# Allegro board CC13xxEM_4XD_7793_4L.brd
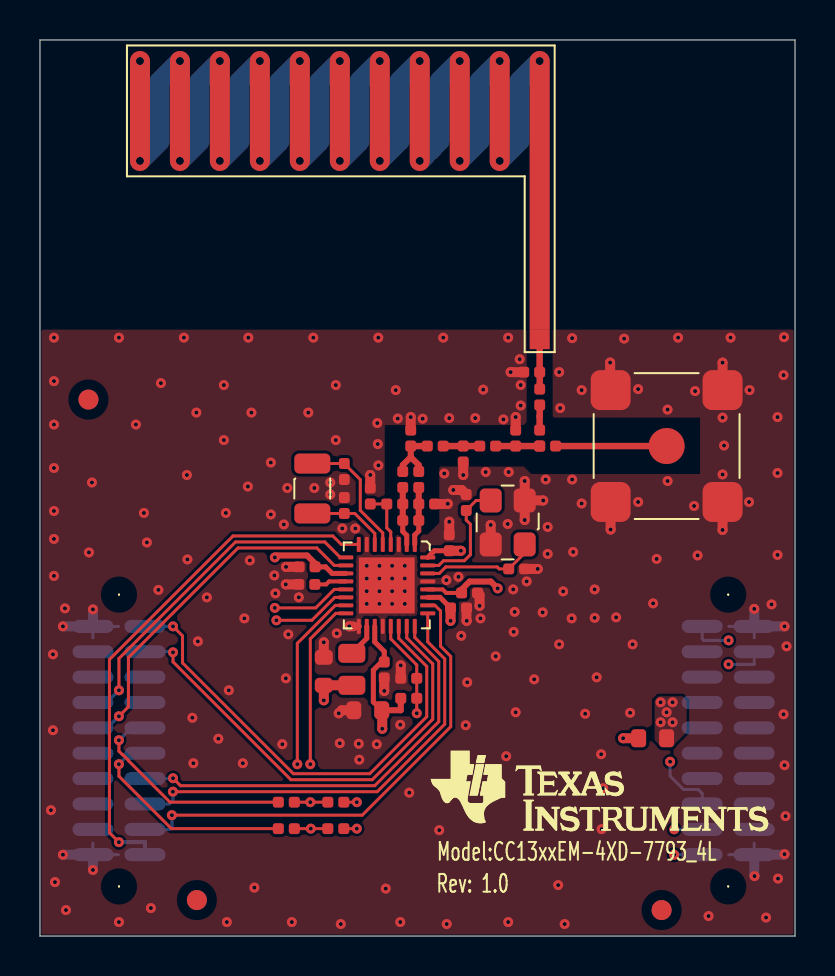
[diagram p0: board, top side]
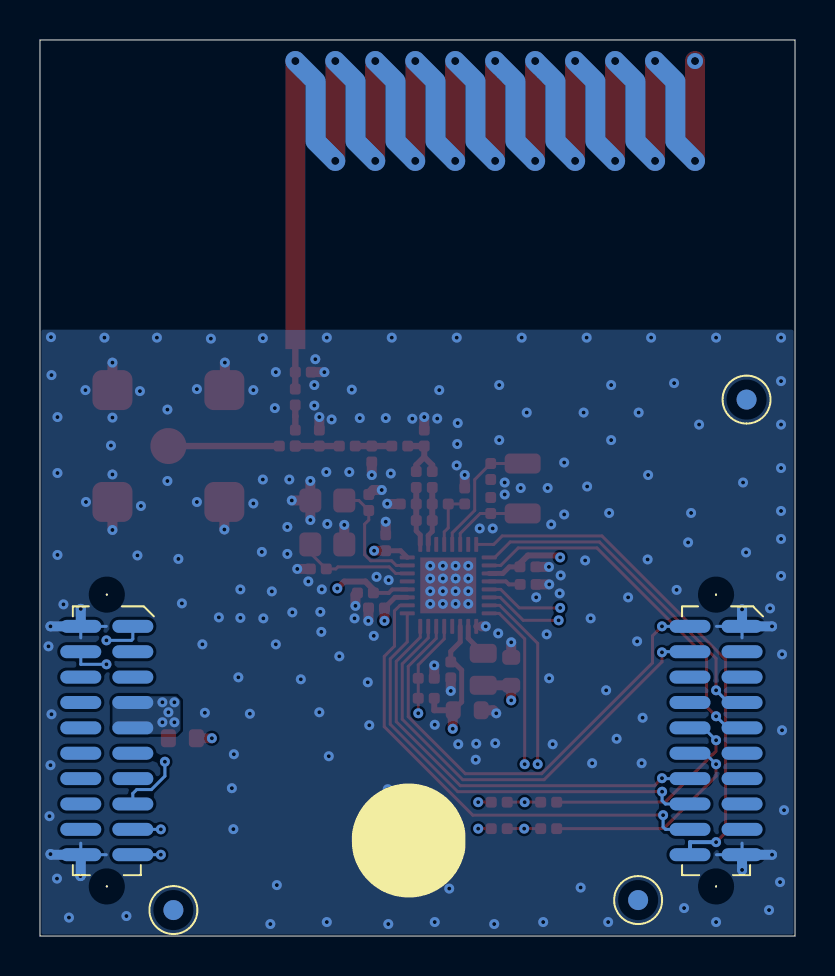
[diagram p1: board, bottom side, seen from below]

Outline 37.78 x 44.85 mm; copper layers: TOP, L2, L3, BOTTOM. Coordinates in mm from the lower left corner of the outline.
Outline path: 0,44.85 0,0 37.78,0 37.78,44.85 0,44.85

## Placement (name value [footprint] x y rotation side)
A1  Antenna PCB helix 868/915MHz  [ANTENNA868_915MHZ_MIRROR_A2N]  25 29.88 0 top
C3  100nF  [CAPC1005X60L]  13.76 18.48 180 top
C4  100nF  [CAPC1005X60L]  20.54 16.42 0 top
C5  22uF  [CAPC1608X100A2L]  17.1 11.3 180 top
C6  100nF  [CAPC1005X60L]  17.22 13.72 270 top
C8  22uF  [CAPC1608X100A2L]  14.2 12.55 90 top
C9  100nF  [CAPC1005X60L]  21.09 17.17 0 top
C11  3.6pF  [CAPC1005X60L]  19.75 21.62 180 top
C12  2.7pF  [CAPC1005X60L]  18.55 24.53 90 top
C13  6.2pF  [CAPC1005X60L]  21.18 23.72 90 top
C14  3pF  [CAPC1005X60L]  23.8 25.33 270 top
C15  100pF  [CAPC1005X60N]  25.8 24.53 180 top
C16  DNM_0402  [CAPC1005X60N]  25 25.33 270 top
C17  12pF  [CAPC1005X60L]  15.23 23.65 270 top
C18  12pF  [CAPC1005X60L]  15.23 21.15 90 top
C19  1uF  [CAPC1005X60L]  13.75 17.6 180 top
C20  100nF  [CAPC1005X60L]  18.85 12.9 180 top
C21  100pF  [CAPC1005X60L]  16.53 21.62 90 top
C22  3.6pF  [CAPC1005X60L]  18.15 22.45 90 top
C23  100nF  [CAPC1005X60L]  20.48 19.28 90 top
C24  DNM  [CAPC1005X60L]  21.33 21.3 90 top
C25  DNM  [CAPC1005X60L]  23.45 18.38 0 top
FIDU1  FIDU_1MM  [FID100X115]  7.85 1.8 0 top
FIDU2  FIDU_1MM  [FID100X115]  2.43 26.85 0 top
FIDU3  FIDU_1MM  [FID100X115]  31.1 1.3 0 top
FIDU4  FIDU_1MM  [FID100X115]  7.85 1.8 180 bottom
FIDU5  FIDU_1MM  [FID100X115]  2.43 26.85 180 bottom
FIDU6  FIDU_1MM  [FID100X115]  31.1 1.3 180 bottom
FL1  BLM18HE152SN1  [FIL_BLM18HE152SN1DL]  29.95 9.9 0 top
J1  SMA-10V21-TGG  [HUSTSAN_SMA10V21TGGAN]  31.35 24.53 0 top
L1  6.8uH  [INDC2012X150L]  15.6 14.15 270 top
L11  27nH  [INDC1005X60L]  18.15 20.8 0 top
L12  7.5nH  [INDC1005X60A2L]  18.95 22.45 90 top
L13  6.8nH  [INDC1005X60L]  19.38 24.53 0 top
L14  6.8nH  [INDC1005X60L]  22 24.53 0 top
L15  TBD  [INDC1005X60L]  25 28.22 180 top
L21  7.5nH  [INDC1005X60A2L]  17.35 21.62 0 top
NOREF  -  []  11.08 0 90 top
NOREF#2  -  []  20.55 9.28 0 top
NOREF#3  -  []  0 44.08 0 top
NOREF#4  -  []  27.45 5.8 180 bottom
P1  SFM-110-02-S-D-A-K-TR  [SAMTEC_SFM11002AN]  2.65 15.5 0 bottom
P2  SFM-110-02-S-D-A-K-TR  [SAMTEC_SFM11002AN]  33.13 15.5 0 bottom
R1  100k  [RESC1005X40L]  18.85 11.9 180 top
R2  0  [RESC1005X40L]  25 26.58 90 top
R3  DNM  [RESC1005X40L]  14.4 6.7 0 top
R4  DNM  [RESC1005X40L]  14.4 5.38 0 top
R5  0  [RESC1005X40N]  11.93 6.7 0 top
R6  0  [RESC1005X40N]  11.93 5.38 0 top
U1  CC13xx 4x4  [QFNFC40P400X400X100-33L]  18.75 19.6 180 top
Y1  32.768kHz  [XTAL_FC-135N]  13.62 23.65 270 top
Y2  24MHz  [OSCCC250X320X80-4L]  24.25 19.6 90 top

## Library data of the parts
A1 = ANTENNA: User Part Number: #PN
C3 C4 C6 C9 C11-C25 = CAPACITOR: alternate symbols: (CAPC1005X60L,CAPC1005X60M)
C5 C8 = CAPACITOR: User Part Number: #PN; alternate symbols: (CAPC1608X100A2L,CAPC1608X100A2M)
FIDU1-FIDU6 = FIDMARK
FL1 = FILTER_2PIN: alternate symbols: (FIL_BLM18HE152SN1DL,FIL_BLM18HE152SN1DM)
J1 = CONN_COAX_1+4: alternate symbols: (HUSTSAN_SMA10V21TGGL,HUSTSAN_SMA10V21TGGM)
L1 = INDUCTOR: alternate symbols: (INDC2012X150L,INDC2012X150M)
L11 L15 = INDUCTOR: alternate symbols: (INDC1005X60M,INDC1005X60L)
L12 L21 = IND_HOR: User Part Number: #PN; alternate symbols: (INDC1005X60A2L,INDC1005X60A2M)
L13 L14 = INDUCTOR: alternate symbols: (INDC1005X60L,INDC1005X60M)
P1 P2 = CONN_HEADER_2X10_P_S
R1-R6 = RESISTOR: alternate symbols: (RESC1005X40L,RESC1005X40M)
U1 = IC_RF_CC13XX_4X4_QFN32: alternate symbols: (QFNFC40P400X400X100-33L,QFNFC40P400X400X100-33M)
Y1 = CRYSTAL: alternate symbols: (XTAL_FC-135L,XTAL_FC-135M)
Y2 = XTAL_TSX_3225_V1: alternate symbols: (OSCCC250X320X80-4L,OSCCC250X320X80-4M)

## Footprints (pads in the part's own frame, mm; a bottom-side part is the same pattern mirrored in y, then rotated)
ANTENNA868_915MHZ_MIRROR_A2N
  rect 1x1 smd: 1(0,0)
CAPC1005X60L
  custom 0.135x0.135 smd: 1(0,0) 2(0.8,0)
CAPC1005X60N
  custom 0.135x0.135 smd: 1(0,0) 2(0.8,0)
CAPC1608X100A2L
  custom 0.188x0.188 smd: 1(0,0) 2(1.4,0)
FID100X115
  oval 1x1 smd: 1(0,0)
FIL_BLM18HE152SN1DL
  custom 0.188x0.188 smd: 1(0,0) 2(1.4,0)
HUSTSAN_SMA10V21TGGAN
  round 1.801 smd: 1(0,0)
  custom 0.5x0.5 smd: 2(-2.8,-2.8) 3(2.8,-2.8) 4(2.8,2.8) 5(-2.8,2.8)
INDC1005X60A2L
  custom 0.135x0.135 smd: 1(0,0) 2(0.8,0)
INDC1005X60L
  custom 0.135x0.135 smd: 1(0,0) 2(0.8,0)
INDC2012X150L
  custom 0.237x0.237 smd: 1(0,0) 2(1.6,0)
OSCCC250X320X80-4L
  custom 0.275x0.275 smd: 1(0,0) 2(2.2,0) 3(2.2,1.7) 4(0,1.7)
QFNFC40P400X400X100-33L
  custom 0.05x0.05 smd: 1(0,0) 2(0.4,0) 3(0.8,0) 4(1.2,0) 5(1.6,0) 6(2,0) 7(2.4,0) 8(2.8,0) 9(3.45,0.65) 10(3.45,1.05) 11(3.45,1.45) 12(3.45,1.85) 13(3.45,2.25) 14(3.45,2.65) 15(3.45,3.05) 16(3.45,3.45) 17(2.8,4.1) 18(2.4,4.1) 19(2,4.1) 20(1.6,4.1) 21(1.2,4.1) 22(0.8,4.1) 23(0.4,4.1) 24(0,4.1) 25(-0.65,3.45) 26(-0.65,3.05) 27(-0.65,2.65) 28(-0.65,2.25) 29(-0.65,1.85) 30(-0.65,1.45) 31(-0.65,1.05) 32(-0.65,0.65)
  rect 2.799x2.799 smd: 33(1.4,2.05)
RESC1005X40L
  custom 0.135x0.135 smd: 1(0,0) 2(0.8,0)
RESC1005X40N
  custom 0.135x0.135 smd: 1(0,0) 2(0.8,0)
SAMTEC_SFM11002AN
  round 0.099 hole 1.501 unplated: (1.302,-1.588) (1.302,13.017)
  oval 2.05x0.65 smd: 1(0,0) 2(2.604,0) 3(0,1.27) 4(2.604,1.27) 5(0,2.54) 6(2.604,2.54) 7(0,3.81) 8(2.604,3.81) 9(0,5.08) 10(2.604,5.08) 11(0,6.35) 12(2.604,6.35) 13(0,7.62) 14(2.604,7.62) 15(0,8.89) 16(2.604,8.89) 17(0,10.16) 18(2.604,10.16) 19(0,11.43) 20(2.604,11.43)
XTAL_FC-135N
  custom 0.25x0.25 smd: 1(0,0) 2(2.5,0)

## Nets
GND: C3.2 C4.2 C5.2 C6.2 C8.2 C9.2 C11.1 C12.2 C13.1 C14.1 C17.2 C18.2 C19.2 C20.2 C21.2 C23.2 C24.2 C25.2 J1.2 J1.3 J1.4 J1.5 L15.2 P1.1 P1.19 P2.2 P2.20 U1.3(VSS#3) U1.7(VSS#7) U1.17(VSS#17) U1.20(VSS#20) U1.29(VSS#29) U1.33(EGP) Y2.2 Y2.4
VDD_EB: FL1.2 P2.7 P2.9
VDDR: C8.1 C9.1 C23.1 L1.2 U1.28(VDDR#28) U1.32(VDDR#32)
VDDS: C3.1 C4.1 C5.1 C6.1 FL1.1 R1.2 U1.11(VDDS2) U1.19(VDDS_DCDC) U1.27(VDDS)
DCDC_SW: L1.1 U1.18(DCDC_SW)
DIO_0: P1.20 U1.8(DIO_0)
DIO_1: P1.7 U1.9(DIO_1)
DIO_2: P1.9 U1.10(DIO_2)
DIO_3: P1.12 R6.1
DIO_3/JTAG_TDO: R4.1 R6.2 U1.15(DIO_3)
DIO_4: P1.10 R5.1
DIO_4/JTAG_TDI: R3.1 R5.2 U1.16(DIO_4)
DIO_5: P1.2 U1.22(DIO_5)
DIO_6: P1.4 U1.23(DIO_6)
DIO_7: P1.14 U1.24(DIO_7)
DIO_8: P1.16 U1.25(DIO_8)
DIO_9: P1.18 U1.26(DIO_9)
JTAG_TCK: P2.1 U1.14(JTAG_TCKC)
JTAG_TDI: P2.17 R3.2
JTAG_TDO: P2.19 R4.2
JTAG_TMS: P2.4 U1.13(JTAG_TMSC)
NRESET: C20.1 P2.15 R1.1 U1.21(RESET_N)
N309359: C19.1 U1.12(DCOUPL)
N310061: C24.1 U1.31(X24M_N) Y2.3
N310119: C25.1 U1.30(X24M_P) Y2.1
N320943: C17.1 U1.5(X32K_Q1) Y1.1
N320947: C18.1 U1.6(X32K_Q2) Y1.2
N473699: C14.2 C15.2 C16.2 L14.2
N473851: C15.1 J1.1
N473855: C11.2 L11.2 L12.1 U1.1(RF_P)
N473863: C22.1 L11.1 L21.2 U1.2(RF_N)
N473875: C12.1 C22.2 L12.2 L13.1
N473891: C13.2 L13.2 L14.1
N473923: A1.1(FEED/GND_1) L15.1 R2.2
N474143: C16.1 R2.1
N475793: C21.1 L21.1 U1.4(RX/TX)

Pads without a net: FIDU1 1; FIDU2 1; FIDU3 1; FIDU4 1; FIDU5 1; FIDU6 1; P1 3 5 6 8 11 13 15 17; P2 3 5 6 8 10 11 12 13 14 16 18

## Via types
v1: diameter 0.5, hole 0.2, TOP to BOTTOM, 254 vias
v2: diameter 0.8, hole 0.4, TOP to BOTTOM, 21 vias

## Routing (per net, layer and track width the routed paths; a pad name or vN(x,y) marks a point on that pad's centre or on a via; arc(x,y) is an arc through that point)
GND: length 38.4
  TOP w0.3: 15.68,15.5 U1.17
  TOP w0.5: C23.2 v1(20.48,20.74) ; C13.1 v1(21.18,23.07) ; Y2.2 v1(24.25,20.82) ; Y2.2 v1(25.18,21.8) ; Y2.2 v1(24.25,22.78) ; C25.2 v1(24.9,18.38) ; C9.2 21.99,17.07 v1(21.99,16.53) ; C21.2 v1(16.53,23.08) ; J1.4 v1(34.15,28.7) ; C11.1 20.39,21.62 v1(20.4,21.64) ; J1.5 28.53,27.35 v1(28.53,28.7) ; L15.2 v1(23.55,28.22) ; v1(34.15,20.33) 34.15,21.72 ; C4.2 21.34,15.79 v1(21.35,15.78) ; C6.2 v1(17.22,12.27) ; Y2.4 v1(22.55,20.58) ; C24.2 21.1,22.33 v1(20.68,22.33) ; v1(18.55,25.97) C12.2 ; C8.2 v1(14.2,14.7) ; C19.2 v1(12.3,17.6) ; C5.2 15.1,11.3 v1(14.95,11.15) ; C20.2 v1(18.05,13.55) ; v1(15.47,15.5) 15.68,15.5 ; v1(12.31,18.48) C3.2 ; v1(23.8,25.98) C14.1 ; 28.55,21.72 v1(28.55,20.35)
  BOTTOM w0.15: 2.65,14.92 P1.1 3.93,15.5 ; 34.46,15.5 P2.2 35.73,14.92 ; 35.73,4.65 P2.20 34.46,4.07 ; 2.65,4.65 P1.19 3.93,4.07
  BOTTOM w0.5: v1(35.73,16.38) P2.2 v1(37.25,15.5) ; v1(2.65,16.35) P1.1 v1(1.15,15.5) ; v1(37.25,4.1) 37.22,4.07 P2.20 35.73,3.02 v1(35.75,3) ; v1(1.15,4.07) P1.19 v1(2.65,3.31)
  vias: v1(0.55,6.3) v1(0.7,29.95) v1(0.7,27.78) v1(0.7,25.6) v1(0.7,23.42) v1(0.7,21.28) v1(0.7,19.88) v1(0.7,18.03) v1(0.65,14.1) v1(0.65,10.3) v1(0.75,2.7) v1(1.25,16.4) v1(1.3,1.3) v1(2.45,19.2) v1(2.6,22.7) v1(3.95,29.95) v1(3.95,0.7) v1(4.8,25.6) v1(5.2,21.17) v1(5.35,19.7) v1(5.55,1.4) v1(5.93,17.33) v1(6.05,27.67) v1(7.2,29.95) v1(7.35,23.08) v1(7.38,18.85) v1(7.62,10.92) v1(7.68,8.65) v1(7.82,26.2) v1(7.9,14.75) v1(8.35,16.95) v1(8.93,9.88) v1(9.2,27.58) v1(9.2,24.82) v1(9.3,21.17) v1(9.35,0.7) v1(9.45,12.3) v1(10.15,8.65) v1(10.23,15.9) v1(10.43,29.95) v1(10.4,22.5) v1(10.5,18.8) v1(10.58,26.2) v1(10.73,2.42) v1(11.55,23.7) v1(11.55,21.1) v1(11.73,18.05) v1(11.78,17.15) v1(12.2,20.6) v1(12.12,9.6) v1(12.38,22.42) v1(12.3,12.9) v1(12.43,15.1) v1(12.6,0.7) v1(12.95,16.95) v1(13.42,26.2) v1(13.68,29.95) v1(13.73,22.42) v1(14.53,22.7) v1(14.53,22.1) v1(14.8,27.58) v1(14.8,24.82) v1(14.85,15.15) v1(15,9.65) v1(15.05,0.6) v1(15.12,20.4) v1(15.78,20.4) v1(15.95,9.62) v1(15.98,8.83) v1(16.35,18.53) v1(16.35,17.89) v1(16.35,17.26) v1(16.35,16.62) v1(16.88,25.67) v1(16.9,24.62) v1(16.85,9.6) v1(16.93,29.95) v1(16.93,23.56) v1(16.98,18.53) v1(16.98,17.89) v1(16.98,17.26) v1(16.98,16.62) v1(17.3,2.38) v1(17.62,18.53) v1(17.62,17.89) v1(17.62,17.26) v1(17.62,16.62) v1(17.8,27.33) v1(17.9,25.9) v1(18.03,10.58) v1(18.03,0.7) v1(18.25,18.53) v1(18.25,17.89) v1(18.25,17.26) v1(18.25,16.62) v1(18.48,7.17) v1(19.15,25.89) v1(19.98,5.3) v1(20.18,29.95) v1(20.23,23.15) v1(20.33,17.81) v1(20.38,7.35) v1(20.35,0.6) v1(20.48,25.92) v1(20.94,17.98) v1(21.08,15.03) v1(21.38,12.7) v1(21.3,10.55) v1(21.78,25.92) v1(22.04,15.9) v1(22.18,27.35) v1(22.3,23.22) v1(22.8,14) v1(23.18,25.86) v1(23.33,9) v1(23.43,29.95) v1(23.45,23.22) v1(23.4,20.62) v1(23.43,0.7) v1(23.68,17.35) v1(23.75,16.22) v1(23.7,15.22) v1(23.8,11.2) v1(24,28.87) v1(24.05,27.58) v1(24.05,26.55) v1(24.35,17.75) v1(24.72,12.85) v1(25.15,16.2) v1(25.3,22.85) v1(25.4,20.47) v1(25.4,19.12) v1(25.97,28.22) v1(25.97,14.6) v1(25.93,2.55) v1(26.03,26.42) v1(26.18,17.25) v1(26.25,0.6) v1(26.6,15.9) v1(26.62,29.92) v1(26.62,22.85) v1(26.68,19.22) v1(27.1,27.33) v1(27.1,21.65) v1(27.28,11.12) v1(27.75,17.35) v1(27.75,15.92) v1(27.85,12.95) v1(28.08,9.1) v1(28.1,5.35) v1(28.18,7.4) v1(28.83,15.95) v1(29.22,29.9) v1(29.53,11.17) v1(29.65,14.6) v1(29.93,27.38) v1(29.93,21.72) v1(30.68,16.65) v1(30.85,18.88) v1(31.4,26.35) v1(31.4,22.78) v1(31.93,29.95) v1(32.78,27.28) v1(32.72,21.53) v1(32.9,19.05) v1(33.45,1) v1(34.15,25.95) v1(34.15,23.1) v1(34.22,24.55) v1(34.55,29.95) v1(35.5,27.33) v1(35.47,21.72) v1(36.33,0.92) v1(36.6,16.6) v1(36.9,25.97) v1(36.9,23.17) v1(36.9,19.08) v1(36.93,2.88) v1(37.22,29.97) v1(37.2,28.08) v1(37.2,11.1) v1(37.25,8.55) v1(37.35,14.5) v1(37.3,6)
VDD_EB:
  vias: v1(31.05,11.7) v1(31.05,10.7) v1(31.35,11.2) v1(31.65,11.7) v1(31.65,10.7)
VDDR: length 22.7
  TOP w0.2: U1.28 20.14,17.35 20.32,17.17 C9.1
  TOP w0.25: C23.1 19.73,19.28 U1.32
  TOP w0.3: C9.1 21.09,17.34 21.49,17.74 22.56,17.74 v1(22.9,17.4)
  TOP w0.5: L1.2 C8.1 v1(14.2,11.8) ; C23.1 v1(21.06,19.28)
  L3 w0.5: v1(21.06,19.28) 22.29,18.05 22.29,18.01 v1(22.9,17.4) 22.9,15.84 19.71,12.65 19.43,12.65 18.4,11.62 16.95,11.62 16.77,11.8 v1(14.2,11.8)
VDDS: length 46.5
  TOP w0.25: C5.1 16.7,11.7 16.68,11.72 16.68,13.31 17.09,13.72 C6.1 17.22,14.25 16.75,14.72 U1.19 ; U1.27 20.01,16.95 C4.1 ; U1.11 14.62,18.15 14.29,18.48 C3.1
  TOP w0.3: v1(11.75,18.95) 11.85,19.05 13.36,19.05 13.76,18.65 C3.1 ; C5.1 18.05,11.3 R1.2
  TOP w0.5: FL1.1 v1(29.18,9.9) ; C5.1 17.12,11.28 v1(17.12,10.38) ; v1(20.54,15.78) C4.1
  L3 w0.5: v1(11.75,18.95) 11.93,19.13 12.58,19.13 13.78,17.93 13.78,16.17 13.8,16.15 ; 13.8,16.15 13.55,15.9 13.55,11.53 14.7,10.38 v1(17.12,10.38) 17.6,9.9 v1(29.18,9.9) ; 13.8,16.15 15.9,16.15 16.28,15.78 v1(20.54,15.78)
DCDC_SW: length 1.7
  TOP w0.25: L1.1 16.35,14.9 U1.18
DIO_0: length 26.5
  TOP w0.15: v1(3.95,4.7) 3.48,5.17 3.48,13.84 9.66,20.03 14.65,20.03 15.08,19.6 U1.8
  BOTTOM w0.2: P1.20 5.25,4.7 v1(3.95,4.7)
DIO_1: length 17.2
  TOP w0.15: U1.9 15.02,18.95 14.25,19.72 9.78,19.72 3.95,13.89 v1(3.95,12.3)
  BOTTOM w0.15: P1.7 3.34,11.69 v1(3.95,12.3)
DIO_2: length 18.2
  TOP w0.15: v1(3.95,11) 4.43,11.47 4.43,13.94 9.91,19.42 13.85,19.42 14.72,18.55 U1.10
  BOTTOM w0.15: v1(3.95,11) 3.37,10.42 P1.9
DIO_3: length 11.2
  TOP w0.15: R6.1 6.58,5.38 3.95,8 v1(3.95,8.6)
  BOTTOM w0.15: v1(3.95,8.6) 4.5,9.15 P1.12
DIO_3/JTAG_TDO: length 14.4
  TOP w0.15: U1.15 14.78,16.55 12.88,14.65 v1(12.88,8.6) ; R4.1 v1(13.55,5.38) R6.2
  L3 w0.15: v1(13.55,5.38) 12.88,6.05 v1(12.88,8.6)
DIO_4: length 11.2
  TOP w0.15: R5.1 6.5,6.7 4.43,8.78 4.43,8.8 4.15,9.08 4.13,9.08 3.95,9.25 v1(3.95,9.8)
  BOTTOM w0.15: P1.10 4.57,10.42 v1(3.95,9.8)
DIO_4/JTAG_TDI: length 12.2
  TOP w0.15: U1.16 14.8,16.15 13.53,14.88 v1(13.53,8.6) ; R5.2 v1(13.53,6.7) R3.1
  L3 w0.15: v1(13.53,6.7) v1(13.53,8.6)
DIO_5: length 24.2
  TOP w0.15: U1.22 17.95,14.9 19.35,13.5 19.35,10.98 16.5,8.12 12.68,8.12 7.13,13.67 7.13,15.03 v1(6.66,15.5)
  BOTTOM w0.15: P1.2 v1(6.66,15.5)
DIO_6: length 23.8
  TOP w0.15: v1(6.66,14.2) 6.66,13.72 12.55,7.83 16.62,7.83 19.65,10.85 19.65,13.62 18.35,14.92 U1.23
  BOTTOM w0.15: v1(6.66,14.2) 6.63,14.23 P1.4
DIO_7: length 21.5
  TOP w0.15: v1(6.66,7.9) 7.03,7.53 16.75,7.53 19.95,10.73 19.95,13.75 18.75,14.95 U1.24
  BOTTOM w0.15: P1.14 6.64,7.88 v1(6.66,7.9)
DIO_8: length 22.8
  TOP w0.15: U1.25 19.4,14.72 20.25,13.87 20.25,10.6 16.87,7.22 v1(6.65,7.22)
  BOTTOM w0.15: P1.16 6.49,6.61 6.65,6.77 v1(6.65,7.22)
DIO_9: length 24.5
  TOP w0.15: v1(6.6,6.05) 16.12,6.05 20.55,10.48 20.55,14 20.04,14.51 20.04,16.27 19.76,16.55 U1.26
  BOTTOM w0.15: P1.18 6.48,5.34 6.6,5.46 v1(6.6,6.05)
JTAG_TCK: length 38.8
  TOP w0.15: U1.14 14.75,16.95 13.6,15.8 v1(11.83,15.8)
  L3 w0.15: v1(34.45,14.8) 33.97,14.33 33.97,10.5 31.72,8.25 15.73,8.25 11.83,12.15 v1(11.83,15.8)
  BOTTOM w0.15: P2.1 33.13,14.87 33.2,14.8 v1(34.45,14.8)
JTAG_TDI: length 18.5
  TOP w0.15: v1(15.85,6.7) R3.2
  L3 w0.15: v1(15.85,6.7) 30.37,6.7 v1(31.73,5.34)
  BOTTOM w0.15: P2.17 v1(31.73,5.34)
JTAG_TDO: length 18.5
  TOP w0.15: R4.2 v1(15.85,5.38)
  L3 w0.15: v1(31.73,4.07) 17.16,4.07 v1(15.85,5.38)
  BOTTOM w0.15: P2.19 v1(31.73,4.07)
JTAG_TMS: length 39.2
  TOP w0.15: v1(11.75,16.42) 13.8,16.42 14.72,17.35 U1.13
  L3 w0.15: v1(11.75,16.42) 11.35,16.03 11.35,12.2 15.6,7.95 31.85,7.95 34.45,10.55 v1(34.45,13.6)
  BOTTOM w0.15: v1(34.45,13.6) 35.73,13.6 P2.4
Net_63:
  vias: v2(23,38.8) v2(25,43.79)
Net_64:
  vias: v2(5,43.79) v2(5,38.8) v2(7,43.79)
Net_65:
  vias: v2(7,38.8) v2(9,43.79)
Net_66:
  vias: v2(9,38.8) v2(11,43.79)
Net_67:
  vias: v2(11,38.8) v2(13,43.79)
Net_68:
  vias: v2(13,38.8) v2(15,43.79)
Net_69:
  vias: v2(15,38.8) v2(17,43.79)
Net_70:
  vias: v2(17,38.8) v2(19,43.79)
Net_71:
  vias: v2(19,38.8) v2(21,43.79)
Net_72:
  vias: v2(21,38.8) v2(23,43.79)
NRESET: length 25.3
  TOP w0.15: U1.21 17.55,14.87 18.85,13.57 C20.1 R1.1 v1(18.85,11.15)
  L3 w0.15: v1(18.85,11.15) 19.88,12.17 31.85,12.17 32.12,11.9 32.12,9.33 v1(31.53,8.72)
  BOTTOM w0.15: v1(31.53,8.72) 31.53,8.01 32.2,7.33 32.94,7.33 33.13,7.14 P2.15
N309359: length 1.6
  TOP w0.2: U1.12 14.47,17.75 14.32,17.6 C19.1
N310061: length 6.1
  TOP w0.15: Y2.3 21.82,21.8 21.33,21.31 C24.1 21.33,20.82 21.53,20.61 21.53,19.09 21.23,18.78 20.19,18.78 19.95,18.55 U1.31
N310119: length 5.8
  TOP w0.15: U1.30 19.98,18.15 20.3,18.47 22.87,18.47 22.97,18.38 C25.1 23.46,18.38 24.25,19.17 Y2.1
N320943: length 6.4
  TOP w0.15: Y1.1 C17.1 15.23,23.64 16.03,22.84 16.03,21.3 17.15,20.18 U1.5
N320947: length 4.1
  TOP w0.15: U1.6 16.75,20.15 15.75,21.15 C18.1 Y1.2
N473699: length 2.2
  TOP w0.32: L14.2 C14.2 C15.2
N473851: length 5.5
  TOP w0.32: C15.1 J1.1
N473855: length 2.9
  TOP w0.25: L11.2 18.95,20.28 18.75,20.08 U1.1
  TOP w0.3: L11.2 C11.2 L12.1
N473863: length 2.9
  TOP w0.25: L11.1 18.15,20.25 18.35,20.05 U1.2
  TOP w0.3: C22.1 L21.2 L11.1
N473875: length 3.2
  TOP w0.3: L12.2 18.95,23.57 18.55,23.97 ; 18.55,23.97 18.15,23.57 C22.2 ; 18.55,23.97 C12.1
  TOP w0.32: C12.1 L13.1
N473891: length 1.8
  TOP w0.32: L14.1 C13.2 L13.2
N473923: length 2.5
  TOP w0.32: A1.1 L15.1 25,28.22 R2.2
N474143: length 1.3
  TOP w0.32: R2.1 25,26.02 25,26.01 C16.1
N475793: length 2.9
  TOP w0.15: U1.4 17.55,20.23 17.35,20.43 L21.1 C21.1

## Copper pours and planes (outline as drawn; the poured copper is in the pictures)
GND on TOP: 0.08,0.08 0.08,30.35 37.7,30.35 37.7,0.08 ; 4 cut-outs
GND on BOTTOM, L2, L3: 0.08,0.08 0.08,30.35 37.7,30.35 37.7,0.08
VDD_EB on TOP: 30.95,12 32.15,12 32.35,11.8 32.35,10.2 31.65,9.5 31.05,9.5 30.75,9.8 30.75,11.8
VDD_EB on BOTTOM: 30.95,12 33.95,12 34.15,11.8 34.15,10.3 33.95,10.1 30.95,10.1 30.75,10.3 30.75,11.8
Net_63 on BOTTOM (solid shape): 24.65,44.15 25.35,44.15 25.35,43.44 24.49,42.57 24.49,39.78 24.45,39.59 24.34,39.43 23.36,38.44 22.65,38.44 22.65,39.15 23.49,39.99 23.49,42.78 23.52,42.97 23.63,43.13
Net_64 on BOTTOM (solid shape): 6.65,44.15 7.36,44.15 7.36,43.44 6.49,42.57 6.49,39.78 6.45,39.59 6.34,39.43 5.36,38.44 4.65,38.44 4.65,39.15 5.49,39.99 5.49,42.78 5.53,42.97 5.64,43.13
Net_65 on BOTTOM (solid shape): 8.65,44.15 9.35,44.15 9.35,43.44 8.49,42.57 8.49,39.78 8.45,39.59 8.34,39.43 7.36,38.44 6.65,38.44 6.65,39.15 7.49,39.99 7.49,42.78 7.53,42.97 7.63,43.13
Net_66 on BOTTOM (solid shape): 10.65,44.15 11.36,44.15 11.36,43.44 10.49,42.57 10.49,39.78 10.45,39.59 10.34,39.43 9.36,38.44 8.65,38.44 8.65,39.15 9.49,39.99 9.49,42.78 9.53,42.97 9.64,43.13
Net_67 on BOTTOM (solid shape): 12.65,44.15 13.35,44.15 13.36,43.44 12.49,42.57 12.49,39.78 12.45,39.59 12.34,39.43 11.36,38.44 10.65,38.44 10.65,39.15 11.49,39.99 11.49,42.78 11.53,42.97 11.63,43.13
Net_68 on BOTTOM (solid shape): 14.65,44.15 15.36,44.15 15.36,43.44 14.49,42.57 14.49,39.78 14.45,39.59 14.34,39.43 13.36,38.44 12.65,38.44 12.65,39.15 13.49,39.99 13.49,42.78 13.53,42.97 13.64,43.13
Net_69 on BOTTOM (solid shape): 16.65,44.15 17.35,44.15 17.36,43.44 16.49,42.57 16.49,39.78 16.45,39.59 16.34,39.43 15.36,38.44 14.65,38.44 14.65,39.15 15.49,39.99 15.49,42.78 15.53,42.97 15.63,43.13
Net_70 on BOTTOM (solid shape): 18.65,44.15 19.35,44.15 19.35,43.44 18.49,42.57 18.49,39.78 18.45,39.59 18.34,39.43 17.36,38.44 16.65,38.44 16.65,39.15 17.49,39.99 17.49,42.78 17.53,42.97 17.63,43.13
Net_71 on BOTTOM (solid shape): 20.65,44.15 21.36,44.15 21.36,43.44 20.49,42.57 20.49,39.78 20.45,39.59 20.34,39.43 19.36,38.44 18.65,38.44 18.65,39.15 19.49,39.99 19.49,42.78 19.53,42.97 19.64,43.13
Net_72 on BOTTOM (solid shape): 22.65,44.15 23.35,44.15 23.36,43.44 22.49,42.57 22.49,39.78 22.45,39.59 22.34,39.43 21.36,38.44 20.65,38.44 20.65,39.15 21.49,39.99 21.49,42.78 21.53,42.97 21.63,43.13

Small or netless copper shapes (teardrops, artwork), in the pictures only: 11 on TOP

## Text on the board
Ref Des/Silkscreen Top: Rev: 1.0 | Model:CC13xxEM-4XD-7793_4L
XSECTION_CHART: *  SURFACE - AIR 0 MM | L1: TOP CONDUCTOR - COPPER 0.035 MM | *  DIELECTRIC - FR-4 0.175 MM | L2: L2 CONDUCTOR - COPPER 0.018 MM | *  DIELECTRIC - FR-4 1.14 MM | L3: L3 CONDUCTOR - COPPER 0.018 MM | L4: BOTTOM CONDUCTOR - COPPER 0.035 MM | DESIGN CROSS SECTION CHART | ___________________________ | TOTAL THICKNESS 1.596 MM
BODY_CENTER: FIGURE | SIZE | 0.2 | 0.4 | 1.501 | DRILL CHART: TOP to BOTTOM | ALL UNITS ARE IN MILLIMETERS | PLATED | NON-PLATED | QTY | 254 | 21 | 4
